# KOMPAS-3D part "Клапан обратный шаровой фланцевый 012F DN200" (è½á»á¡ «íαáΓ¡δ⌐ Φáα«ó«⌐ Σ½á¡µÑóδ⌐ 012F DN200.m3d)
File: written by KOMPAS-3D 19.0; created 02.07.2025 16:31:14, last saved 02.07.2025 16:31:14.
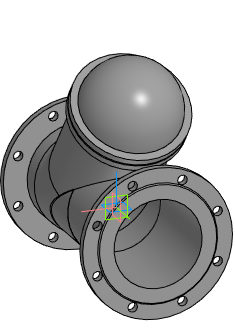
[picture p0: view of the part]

Document properties: Полное имя файла: E:\Dendor Работа Сачек\3D для проектировщиков\5.3 Тип 012F, 012F.Z Клапан обратный шаровой фланцевый\stp_Клапан обратный шаровой фланцевый 012F\Клапан обратный шаровой фланцевый 012F DN200.m3d

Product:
- Part/product: Клапан обратный шаровой фланцевый 012F DN200

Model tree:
1. Операция без истории:1  (labels: Клапан обратный шаровой фланцевый 012F DN200)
